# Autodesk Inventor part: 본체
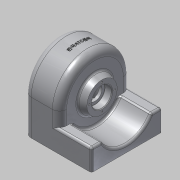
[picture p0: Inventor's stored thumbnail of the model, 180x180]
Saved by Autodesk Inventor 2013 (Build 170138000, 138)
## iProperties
Created: 2015-02
Part Number: 본체
Material: 알루미늄 6061
Document SubType Name: Modeling
Designer: Administrator
Density: 1 g/cm^3
Author: Administrator
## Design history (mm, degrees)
sketch "스케치1"
  geometry: L1 (-50, -25)-(50, -25); L2 (50, -25)-(50, 25); L3 (50, 25)-(-50, 25); L4 (-50, 25)-(-50, -25); L5 (-50, -25)-(50, 25); L6 (50, -25)-(-50, 25); A1 r 50 centre (0, 25) between (50, 25) and (-50, 25); 1 further point
  constraints: 12 end point, 3 midpoint, 2 parallel, 2 point on circle, 1 centre point, 1 horizontal, 1 perpendicular
  dimensions: "d0" = 100 distance of L1.start L1.end; "d2" = 50 distance of L3.end L1.start
extrude "돌출2" new body sketch "스케치1" distance "d7" = 50; taper "d8" = 0 deg
sketch "스케치3"
  geometry: L1 (-25, -50)-(25, -50) reference; L2 (25, -50)-(25, 50) reference; L3 (25, 50)-(-25, 50) reference; L4 (25, -50)-(-5, -50); L5 (-5, -50)-(-5, -34.641); L6 (25, 50)-(-5, 50); L7 (-5, 50)-(-5, 34.641); L8 (25, -50)-(25, 50); A1 r 50 centre (-25, 0) between (-25, 50) and (-25, -50) reference; A2 r 40 centre (-25, 0) between (-5, -34.641) and (-5, 34.641); 1 further point
  constraints: 10 end point, 2 perpendicular, 2 point on circle, 2 point on line, 1 centre point, 1 coincident, 1 collinear
  dimensions: "d9" = 80 diameter of A2; "d10" = 30 distance of L1.end L4.end; "d11" = 30 distance of L2.end L6.end
extrude "돌출3" join sketch "스케치3" distance "d12" = 45; taper "d13" = 0 deg
sketch "스케치5"
  geometry: C1 r 20 at (25, 0); A1 r 50 centre (25, 0) between (25, -50) and (25, 50) reference; 1 further point
  constraints: 1 centre point, 1 coincident
  dimensions: "d14" = 40 diameter of C1
extrude "돌출4" join sketch "스케치5" distance "d15" = 9; taper "d16" = 0 deg
node "작업 평면1"
sketch "스케치6"
  geometry: L1 (50, -50)-(50, 0) reference; L2 (50, 0)-(50, 20) reference; L3 (50, 20)-(50, 40) reference; L4 (50, 0)-(60, 0); L5 (50, 0)-(50, -25); L6 (50, -25)-(60, -21.36); L7 (60, -21.36)-(60, 0); L8 (0, 0)-(0, 0) reference; L9 (0, 0)-(50, 0) reference; L10 (50, 0)-(50, 0) reference; L11 (0, 0)-(50, 0) reference; 1 further point
  constraints: 8 end point, 1 midpoint, 1 parallel, 1 perpendicular
  dimensions: "d17" = 10 distance of L1.end L4.end; "d18" = 25 distance of L1.end L5.end; "d19" = 110 deg angle of L1 L6
revolve "회전1" sketch "스케치6" stored, may be unused: angle "d20" = 90 deg
sketch "스케치7"
  geometry: L1 (0, 0)-(0, 100) reference; L2 (0, 100)-(-95, 100) reference; L3 (-46, 96)-(-4, 96); L4 (-4, 96)-(-4, 4); L5 (-4, 4)-(-46, 4); L6 (-46, 4)-(-46, 96); 1 further point
  constraints: 8 end point, 2 parallel, 1 horizontal, 1 perpendicular
  dimensions: "d21" = 42 distance of L3.start L3.end; "d23" = 92 distance between parallel lines of L5 L3; "d24" = 4 distance between parallel lines of L3 L2; "d25" = 4 distance between parallel lines of L1 L4
extrude "돌출5" cut sketch "스케치7" distance "d26" = 50; taper "d27" = 0 deg
node "작업 평면2"
sketch "스케치9"
  geometry: L1 (25, -46)-(25, 46) reference; L2 (25, 46)-(25, -46); A1 r 46 centre (25, 0) between (25, -46) and (25, 46); A2 r 50 centre (25, 0) between (25, -50) and (25, 50) reference; 1 further point
  constraints: 2 end point, 2 point on circle, 1 centre point, 1 collinear, 1 midpoint
extrude "돌출6" cut sketch "스케치9" stored distance "d29" = 42; taper "d30" = 0 deg
sketch "스케치10"
  geometry: C1 r 21.36 at (0, 0) reference; 2 further points
  constraints: 1 coincident
hole "구멍1" sketch "스케치10" at (0, 0) diameter "d31" = 20; stored, may be unused: countersink angle "d35" = 90 deg, drill point angle "d37" = 0 deg; dims "d32" = 6, "d33" = 28, "d34" = 10, "d36" = 4
sketch "스케치11"
  geometry: L1 (0, 0)-(-18, 0); C1 r 14 at (0, 0) reference; C2 r 21.36 at (0, 0) reference; 5 further points
  constraints: 2 end point, 1 coincident, 1 horizontal, 5 other
  dimensions: "d38" = 18 distance of L1.start L1.end; "d41" = 360 deg dimension on C1.centre point (-18, 0) (derived)
hole "구멍2" sketch "스케치11" at (0, 18), (18, 0), (0, -18), (-18, 0) diameter "d43" = 2.459; stored, may be unused: countersink angle "d47" = 90 deg, drill point angle "d49" = 118 deg; dims "d44" = 6, "d45" = 28, "d46" = 10, "d48" = 9
sketch "스케치13"
  geometry: L1 (4, 0)-(4, -46) reference; L2 (4, 0)-(-6, 0); L3 (-6, 0)-(-6, -10); L4 (-6, -10)-(-4, -10); L5 (-4, -10)-(-4, -14); L6 (-4, -14)-(4, -14); L7 (4, -14)-(4, 0); 1 further point
  constraints: 12 end point, 4 perpendicular, 1 collinear, 1 parallel, 1 point on line
  dimensions: "d50" = 10 distance of L1.start L2.end; "d51" = 10 distance of L2.end L3.end; "d52" = 2 distance of L3.end L4.end; "d53" = 4 distance of L4.end L5.end
revolve "회전2" sketch "스케치13" stored, may be unused: angle "d54" = 90 deg
sketch "스케치14"
  geometry: L1 (0, 100)-(-95, 100) reference; L2 (-95, 0)-(-95, 100) reference; 5 further points
  constraints: 2 horizontal alignment, 2 vertical alignment
  dimensions: "d55" = 33 distance of point (-53, 91.75) point (-86, 91.75); "d57" = 83.5 distance of point (-86, 91.75) point (-86, 8.25); "d58" = 9 distance from line of L2 point (-86, 91.75); "d59" = 8.25 distance from line of L1 point (-86, 91.75)
hole "구멍3" sketch "스케치14" at (-86, 8.25), (-86, 91.75), (-53, 91.75), (-53, 8.25) diameter "d60" = 5.134; stored, may be unused: countersink angle "d64" = 90 deg, drill point angle "d66" = 118 deg; dims "d61" = 10, "d62" = 4, "d63" = 2, "d65" = 13
node "작업 평면3"
sketch "스케치15"
  geometry: 2 further points
  constraints: 1 other
feature "엠보싱1" sketch "스케치15" dims "d0" = 100, "d2" = 50, "d13" = 0, "d67" = 0.5, "d68" = 0
fillet "모깎기1" dims "d69" = 10
fillet "모깎기2" dims "d70" = 6
fillet "모깎기3" dims "d71" = 3
fillet "모깎기4" dims "d72" = 3
chamfer "모따기1" distance "d73" = 1; stored, may be unused: second distance "d74" = 2, angle "d75" = 45 deg
fillet "모깎기5" dims "d76" = 0.3
fillet "모깎기6" dims "d77" = 3
fillet "모깎기7" dims "d78" = 0.3
fillet "모깎기8" dims "d79" = 3
node "솔리드2"
node "투영된 루프1"
